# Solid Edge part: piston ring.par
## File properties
Author: Robert a Rhodes jr
Template: Normal.par
Last saved by: Cadcim
Revision: 9
Application: Solid Edge
Accuracy: 0.99
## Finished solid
Body 1: solid body, 6 faces, 12 edges, 8 vertices.
  Faces by surface: plane 4, cylinder 2
  Edges by curve: line 8, circle 4
Bounding box of the edges (mm): 94.000 x 94.000 x 3.000, from (-47, -47, -3) to (47, 47, 0).
Cylindrical faces by radius (mm): R43 x1, R47 x1
Planar faces by outward normal: +y 1, +z 1, -y 1, -z 1
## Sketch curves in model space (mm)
line (-28.0593, 0, 0) -> (-28.0593, -1, 0)
line (-28.0593, -1, 0) -> (-54.5597, -1, 0)
line (-54.5597, -1, 0) -> (-54.5597, 0, 0)
line (-54.5597, 0, 0) -> (-28.0593, 0, 0)
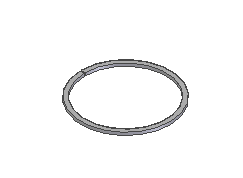
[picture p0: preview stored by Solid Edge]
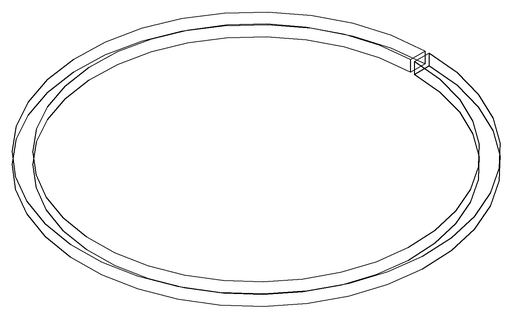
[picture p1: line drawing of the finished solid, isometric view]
